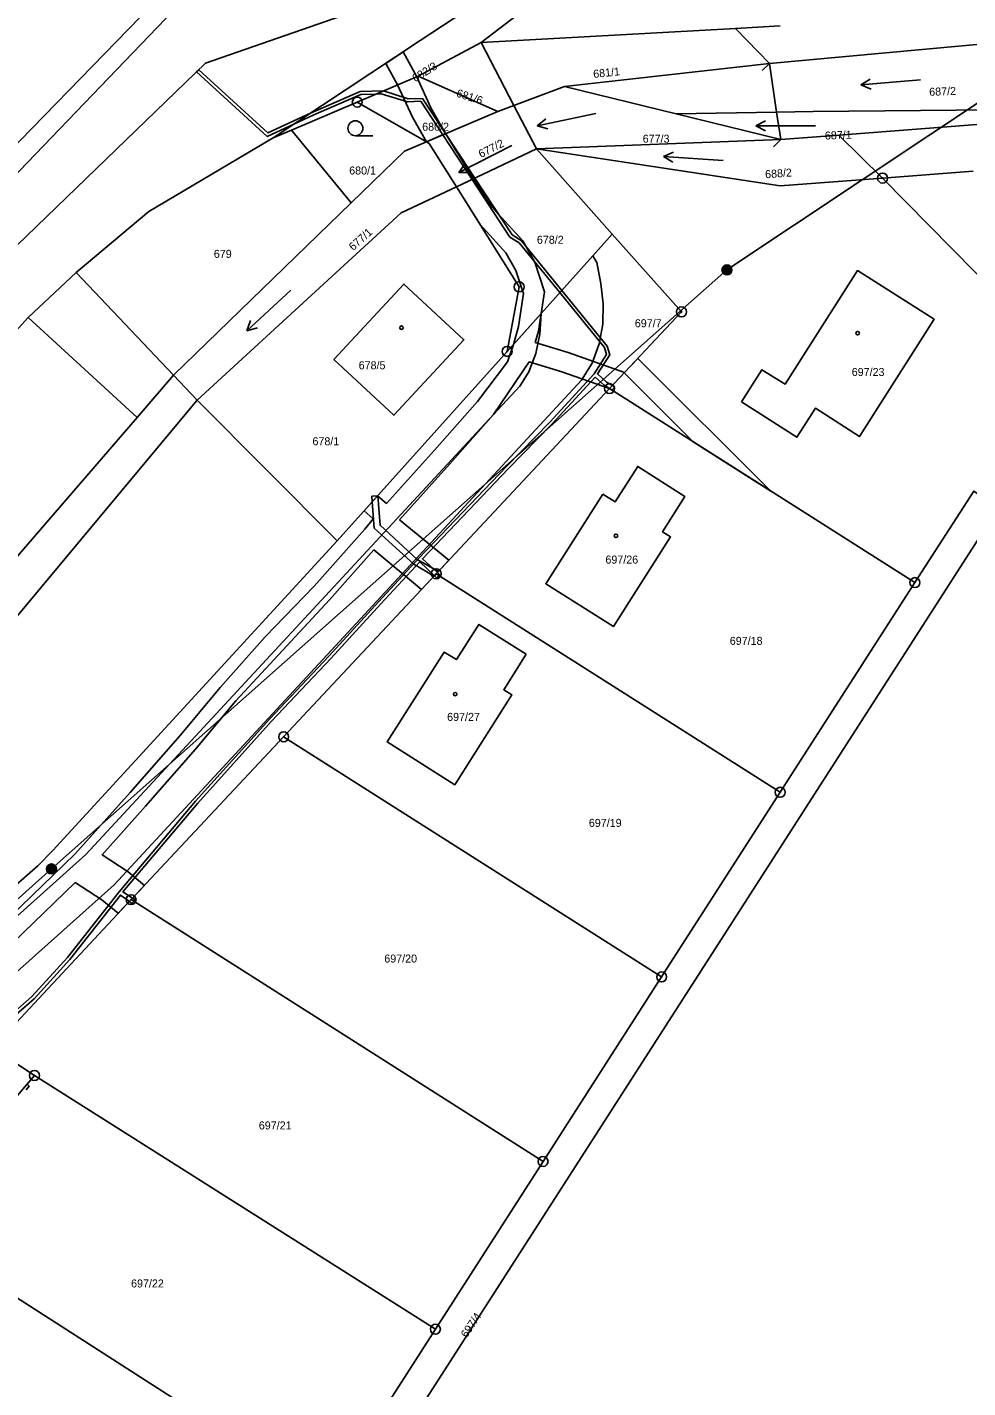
# Model space of a CAD drawing. Extents: x -587171 to -555306, y -1167727 to -1074732.
# Drawn here: x -560808.1 to -560713.8, y -1077994 to -1077857.5 of the extents above; entities that cross this region are included whole.
import ezdxf

# ---------------------------------------------------------------- set-up
doc = ezdxf.new("R2010")
doc.units = 0
for name, color, linetype in [('Hranice parcel', 7, 'Continuous'), ('Parcelní čísla', 7, 'Continuous'), ('Poz předměty', 7, 'Continuous'), ('Vnitřní kresba', 7, 'Continuous'), ('Věcná břemena k části', 7, 'Continuous'), ('Značky bodu BP', 7, 'Continuous'), ('Značky budov', 7, 'Continuous'), ('Značky kultur', 7, 'Continuous')]:
    doc.layers.add(name, color=color, linetype=linetype)

msp = doc.modelspace()

# ---------------------------------------------------------------- linework, layer by layer
at = {"layer": 'Hranice parcel'}
for p, q in [((-560756.08, -1077854.03), (-560762.56, -1077859.03)), ((-560733.66, -1077861.13), (-560679.72, -1077856.25)), ((-560762.56, -1077859.03), (-560737.05, -1077857.63)), ((-560737.05, -1077857.63), (-560732.58, -1077857.38)), ((-560733.66, -1077861.13), (-560737.05, -1077857.63)), ((-560762.56, -1077859.03), (-560768.88, -1077862.42)), ((-560759.28, -1077865.35), (-560762.56, -1077859.03)), ((-560790.19, -1077861.11), (-560821.39, -1077891.23)), ((-560754.21, -1077863.45), (-560733.66, -1077861.13)), ((-560768.88, -1077862.42), (-560774.98, -1077865.02)), ((-560760.9, -1077865.96), (-560768.88, -1077862.42)), ((-560754.21, -1077863.45), (-560759.28, -1077865.35)), ((-560743, -1077866.2), (-560754.21, -1077863.45)), ((-560774.98, -1077865.02), (-560781.58, -1077867.83)), ((-560768.05, -1077869), (-560774.98, -1077865.02)), ((-560726.71, -1077868.33), (-560672, -1077864.07)), ((-560760.9, -1077865.96), (-560768.05, -1077869)), ((-560759.28, -1077865.35), (-560760.9, -1077865.96)), ((-560757.02, -1077869.71), (-560759.28, -1077865.35)), ((-560732.52, -1077868.78), (-560743, -1077866.2)), ((-560781.58, -1077867.83), (-560783.41, -1077868.61)), ((-560775.58, -1077875.11), (-560781.58, -1077867.83)), ((-560757.02, -1077869.71), (-560732.52, -1077868.78)), ((-560732.52, -1077868.78), (-560726.71, -1077868.33)), ((-560726.71, -1077868.33), (-560722.31, -1077872.64)), ((-560765.04, -1077873.51), (-560757.02, -1077869.71)), ((-560749.41, -1077878.26), (-560757.02, -1077869.71)), ((-560713.23, -1077871.95), (-560722.31, -1077872.64)), ((-560722.31, -1077872.64), (-560693.81, -1077901.67)), ((-560793.41, -1077892.41), (-560775.58, -1077875.11)), ((-560749.41, -1077878.26), (-560751.37, -1077880.45)), ((-560756.54, -1077886.22), (-560751.37, -1077880.45)), ((-560793.41, -1077892.41), (-560803.17, -1077882.12)), ((-560759.95, -1077890.02), (-560756.54, -1077886.22)), ((-560776.98, -1077909.03), (-560759.95, -1077890.02)), ((-560791.02, -1077894.93), (-560793.41, -1077892.41)), ((-560767.06, -1077912.33), (-560749.68, -1077893.76)), ((-560749.68, -1077893.76), (-560719.07, -1077913.22)), ((-560791.02, -1077894.93), (-560842.84, -1077957.02)), ((-560776.98, -1077909.03), (-560791.02, -1077894.93)), ((-560768, -1077994.99), (-560710.72, -1077905.75)), ((-560782.36, -1077928.68), (-560767.06, -1077912.33)), ((-560767.06, -1077912.33), (-560732.58, -1077934.25)), ((-560719.07, -1077913.22), (-560732.58, -1077934.25)), ((-560797.66, -1077945.02), (-560782.36, -1077928.68)), ((-560782.36, -1077928.68), (-560744.46, -1077952.77)), ((-560732.58, -1077934.25), (-560744.46, -1077952.77)), ((-560797.66, -1077945.02), (-560756.35, -1077971.28)), ((-560744.46, -1077952.77), (-560756.35, -1077971.28)), ((-560809.85, -1077965.61), (-560807.35, -1077962.66)), ((-560807.35, -1077962.66), (-560767.15, -1077988.11)), ((-560756.35, -1077971.28), (-560767.15, -1077988.11)), ((-560777.96, -1078004.94), (-560820.22, -1077977.81)), ((-560767.15, -1077988.11), (-560777.96, -1078004.94))]:
    msp.add_line(p, q, dxfattribs=at)
for points in [[(-560839.79, -1077904.03), (-560830.06, -1077893.99), (-560794.22, -1077856.67), (-560783.34, -1077845.34)], [(-560831.7, -1077892.42), (-560795.51, -1077855.24), (-560804.32, -1077846.62), (-560836.42, -1077879.93), (-560837.53, -1077878.9), (-560844.57, -1077886.1), (-560839.95, -1077890.45), (-560834.16, -1077895.9), (-560831.33, -1077893.15), (-560831.89, -1077892.61), (-560831.7, -1077892.42)], [(-560759.81, -1077848.36), (-560774.13, -1077855.53), (-560790.19, -1077861.11)], [(-560783.41, -1077868.61), (-560768.67, -1077858.85), (-560757.69, -1077851.58)], [(-560672, -1077864.07), (-560707.75, -1077865.76), (-560729.28, -1077865.96), (-560732.93, -1077866.02), (-560743, -1077866.2)], [(-560783.41, -1077868.61), (-560795.88, -1077876), (-560803.17, -1077882.12)], [(-560768.05, -1077869), (-560770.26, -1077869.94), (-560775.58, -1077875.11)], [(-560765.04, -1077873.51), (-560767.76, -1077869.17), (-560768.05, -1077869)], [(-560722.31, -1077872.64), (-560732.58, -1077873.43), (-560757.02, -1077869.71)], [(-560791.02, -1077894.93), (-560770.59, -1077876.13), (-560765.04, -1077873.51)], [(-560759.95, -1077890.02), (-560758.75, -1077883.55), (-560765.04, -1077873.51)], [(-560749.68, -1077893.76), (-560742.47, -1077886.06), (-560749.41, -1077878.26)], [(-560751.37, -1077880.45), (-560750.95, -1077881.11), (-560750.55, -1077883.22), (-560750.31, -1077885.24), (-560750.36, -1077887.28), (-560750.72, -1077889.27), (-560751.42, -1077891.19), (-560752.5, -1077892.91), (-560799.37, -1077943.53), (-560809.44, -1077952.55), (-560810.66, -1077954.11), (-560811.42, -1077955.96), (-560811.86, -1077957.91), (-560811.93, -1077959.9), (-560811.62, -1077961.87), (-560810.89, -1077963.73), (-560809.85, -1077965.61)], [(-560803.17, -1077882.12), (-560807.98, -1077886.64), (-560824.5, -1077904.81), (-560849.79, -1077930.17)], [(-560736.46, -1077895.08), (-560734.41, -1077891.87), (-560732.08, -1077893.32), (-560724.83, -1077881.92), (-560717.15, -1077886.8), (-560724.62, -1077898.55), (-560729.05, -1077895.73), (-560730.9, -1077898.64), (-560736.46, -1077895.08)], [(-560777.34, -1077890.83), (-560770.3, -1077883.27), (-560764.28, -1077888.86), (-560771.33, -1077896.43), (-560777.34, -1077890.83)], [(-560756.54, -1077886.22), (-560756.66, -1077888.29), (-560757.06, -1077890.24), (-560757.78, -1077892.08), (-560758.67, -1077893.52), (-560761.33, -1077896.34), (-560802.19, -1077940.49), (-560832.27, -1077967.48), (-560829.54, -1077970.6), (-560825.47, -1077966.88), (-560821.58, -1077966.02), (-560819.57, -1077966.1), (-560816.7, -1077966.95), (-560814.91, -1077967.81), (-560813.35, -1077969.09), (-560809.85, -1077965.61)], [(-560836.88, -1077942.81), (-560797.05, -1077896.64), (-560793.41, -1077892.41)], [(-560750.35, -1077904.33), (-560749.12, -1077905.1), (-560746.85, -1077901.56), (-560742.12, -1077904.59), (-560744.37, -1077908.13), (-560743.57, -1077908.64), (-560749.3, -1077917.62), (-560756.08, -1077913.33), (-560750.35, -1077904.33)], [(-560710.72, -1077905.75), (-560713.17, -1077904.03), (-560719.07, -1077913.22)], [(-560834.1, -1077965.37), (-560807, -1077941.64), (-560805.52, -1077940.09), (-560776.98, -1077909.03)], [(-560758.05, -1077920.41), (-560760.3, -1077923.96), (-560759.49, -1077924.47), (-560765.21, -1077933.49), (-560771.97, -1077929.2), (-560766.25, -1077920.18), (-560765.04, -1077920.94), (-560762.78, -1077917.41), (-560758.05, -1077920.41)], [(-560807.35, -1077962.66), (-560811.56, -1077959.88), (-560797.66, -1077945.02)]]:
    msp.add_lwpolyline(points, dxfattribs=at)
at = {"layer": 'Poz předměty'}
for p, q in [((-560737.91, -1077881.85), (-560693.9, -1077852.52)), ((-560805.64, -1077941.94), (-560737.91, -1077881.85)), ((-560872.99, -1078001.92), (-560805.64, -1077941.94))]:
    msp.add_line(p, q, dxfattribs=at)
for centre, radius in [((-560737.91, -1077881.85), 0.5), ((-560737.91, -1077881.85), 0.4), ((-560737.91, -1077881.85), 0.3), ((-560737.91, -1077881.85), 0.2), ((-560737.91, -1077881.85), 0.1), ((-560805.64, -1077941.94), 0.5), ((-560805.64, -1077941.94), 0.4), ((-560805.64, -1077941.94), 0.3), ((-560805.64, -1077941.94), 0.2), ((-560805.64, -1077941.94), 0.1)]:
    msp.add_circle(centre, radius, dxfattribs=at)
at = {"layer": 'Vnitřní kresba'}
for p, q in [((-560734.37, -1077861.84), (-560733.66, -1077861.13)), ((-560733.66, -1077861.13), (-560732.93, -1077866.02)), ((-560732.93, -1077866.02), (-560732.52, -1077868.78)), ((-560733.23, -1077869.49), (-560732.52, -1077868.78)), ((-560797.05, -1077896.64), (-560807.98, -1077886.64))]:
    msp.add_line(p, q, dxfattribs=at)
at = {"layer": 'Věcná břemena k části'}
for points in [[(-560768.05, -1077869), (-560766.13, -1077868.18), (-560767.61, -1077865.59), (-560769, -1077862.47), (-560770.38, -1077859.98), (-560772.11, -1077861.13), (-560770.93, -1077863.29), (-560769.45, -1077866.53)], [(-560781.34, -1077867.24), (-560779.32, -1077866.31), (-560774.62, -1077864.25), (-560773.09, -1077864.21), (-560772.57, -1077864.2), (-560769.93, -1077864.98), (-560768.61, -1077864.94), (-560766.4, -1077868.3), (-560766.12, -1077868.18), (-560768.45, -1077864.64), (-560769.89, -1077864.68), (-560772.34, -1077863.9), (-560774.68, -1077863.95), (-560779.66, -1077866.14), (-560783.95, -1077868.11), (-560790.87, -1077861.77), (-560791.1, -1077861.99), (-560784.01, -1077868.47)], [(-560768.05, -1077869), (-560767.76, -1077869.17), (-560765.04, -1077873.51), (-560763.34, -1077872.7), (-560765.23, -1077869.65), (-560766.13, -1077868.18)], [(-560763.47, -1077872.77), (-560763.2, -1077872.64), (-560766.12, -1077868.18), (-560766.4, -1077868.3)], [(-560759.32, -1077889.32), (-560756.54, -1077886.22), (-560756.22, -1077884.05), (-560757.18, -1077881.06), (-560758.39, -1077878.92), (-560760.88, -1077876.19), (-560761.85, -1077875.03), (-560763.34, -1077872.7), (-560765.04, -1077873.51), (-560762.67, -1077877.29), (-560760.07, -1077880.14), (-560759.08, -1077881.9), (-560758.32, -1077884.23), (-560758.83, -1077887.54)], [(-560758.75, -1077879.12), (-560754.68, -1077884.13), (-560754.47, -1077883.91), (-560758.55, -1077878.9), (-560759.46, -1077878.33), (-560763.2, -1077872.64), (-560763.47, -1077872.77), (-560759.68, -1077878.55)], [(-560746.84, -1077890.73), (-560748.21, -1077892.19), (-560741.3, -1077899.09), (-560733.51, -1077904.04)], [(-560749.14, -1077893.57), (-560749.38, -1077893.44), (-560749.68, -1077893.76), (-560749.45, -1077893.91)], [(-560773.52, -1077904.54), (-560773.48, -1077905.12), (-560772.92, -1077904.5)], [(-560766.85, -1077912.1), (-560768.96, -1077910.9), (-560772.69, -1077907.47), (-560772.92, -1077904.5), (-560773.48, -1077905.12), (-560773.27, -1077907.76), (-560769.32, -1077911.38), (-560767.27, -1077912.56), (-560767.06, -1077912.33)]]:
    msp.add_lwpolyline(points, close=True, dxfattribs=at)
for points in [[(-560809.41, -1077956.73), (-560807.39, -1077954.96), (-560803.81, -1077951.03), (-560798.72, -1077944.56), (-560797.83, -1077945.21), (-560797.57, -1077945.4), (-560797.39, -1077945.19), (-560797.25, -1077945.04), (-560797.52, -1077944.87), (-560798.47, -1077944.25), (-560790.97, -1077935.33), (-560783.57, -1077927.1), (-560777.6, -1077920.79), (-560772.63, -1077915.33), (-560768.72, -1077911.12), (-560767.25, -1077912.54), (-560767.01, -1077912.77), (-560766.77, -1077912.52), (-560766.69, -1077912.44), (-560766.95, -1077912.21), (-560768.44, -1077910.83), (-560759.8, -1077901.78), (-560755.46, -1077897.32), (-560751.14, -1077892.61), (-560750.23, -1077893.42), (-560749.68, -1077893.76), (-560749.38, -1077893.44), (-560749.99, -1077893.1), (-560750.9, -1077892.29), (-560749.66, -1077890.36), (-560749.94, -1077889.49), (-560754.47, -1077883.91), (-560754.68, -1077884.13), (-560750.2, -1077889.63), (-560749.98, -1077890.32), (-560751.24, -1077892.27), (-560755.68, -1077897.12), (-560760.02, -1077901.58), (-560768.8, -1077910.77), (-560772.85, -1077915.13), (-560777.82, -1077920.59), (-560783.79, -1077926.9), (-560791.19, -1077935.13), (-560798.84, -1077944.22), (-560804.03, -1077950.83), (-560807.6, -1077954.74), (-560809.61, -1077956.51)], [(-560810.56, -1077950.36), (-560803.27, -1077943.3), (-560800.59, -1077945.05), (-560798.94, -1077946.39), (-560797.66, -1077945.02), (-560796.32, -1077943.59), (-560797.94, -1077942.24), (-560800.57, -1077940.52), (-560796.21, -1077935.64), (-560791.19, -1077929.91), (-560787.15, -1077925.07), (-560777.77, -1077914.96), (-560773.31, -1077909.94), (-560768.55, -1077913.92), (-560767.06, -1077912.33), (-560765.79, -1077910.97), (-560770.73, -1077906.91), (-560765.69, -1077901.29), (-560761.33, -1077896.34), (-560757.75, -1077891.08), (-560754.47, -1077892.07), (-560749.68, -1077893.76), (-560748.17, -1077892.14), (-560753.83, -1077890.13), (-560757.13, -1077889.14), (-560756.81, -1077887.98), (-560756.54, -1077886.22), (-560759.32, -1077889.32), (-560759.93, -1077891.06), (-560762.93, -1077895.04), (-560767.23, -1077899.93), (-560772.04, -1077905.28), (-560772.94, -1077904.52), (-560774.29, -1077906.03), (-560773.37, -1077906.81), (-560774.22, -1077907.85), (-560779.29, -1077913.56), (-560784.2, -1077918.66), (-560788.71, -1077923.73), (-560792.75, -1077928.57), (-560797.75, -1077934.28), (-560803.29, -1077940.46), (-560811.98, -1077948.86)], [(-560808.19, -1077964.1), (-560807.88, -1077963.74), (-560808.08, -1077963.52)]]:
    msp.add_lwpolyline(points, dxfattribs=at)
at = {"layer": 'Značky bodu BP'}
for centre, radius in [((-560774.98, -1077865.02), 0.5), ((-560774.98, -1077865.02), 0.0303), ((-560722.31, -1077872.64), 0.5), ((-560722.31, -1077872.64), 0.0303), ((-560758.75, -1077883.55), 0.5), ((-560758.75, -1077883.55), 0.0303), ((-560742.47, -1077886.06), 0.5), ((-560742.47, -1077886.06), 0.0303), ((-560759.95, -1077890.02), 0.5), ((-560759.95, -1077890.02), 0.0303), ((-560749.68, -1077893.76), 0.5), ((-560749.68, -1077893.76), 0.0303), ((-560767.06, -1077912.33), 0.5), ((-560767.06, -1077912.33), 0.0303), ((-560719.07, -1077913.22), 0.5), ((-560719.07, -1077913.22), 0.0303), ((-560782.36, -1077928.68), 0.5), ((-560782.36, -1077928.68), 0.0303), ((-560732.58, -1077934.25), 0.5), ((-560732.58, -1077934.25), 0.0303), ((-560797.66, -1077945.02), 0.5), ((-560797.66, -1077945.02), 0.0303), ((-560744.46, -1077952.77), 0.5), ((-560744.46, -1077952.77), 0.0303), ((-560807.35, -1077962.66), 0.5), ((-560807.35, -1077962.66), 0.0303), ((-560756.35, -1077971.28), 0.5), ((-560756.35, -1077971.28), 0.0303), ((-560767.15, -1077988.11), 0.5), ((-560767.15, -1077988.11), 0.0303)]:
    msp.add_circle(centre, radius, dxfattribs=at)
at = {"layer": 'Značky budov'}
for centre in [(-560770.55, -1077887.65), (-560724.81, -1077888.2), (-560749.04, -1077908.53), (-560765.16, -1077924.4)]:
    msp.add_circle(centre, 0.175, dxfattribs=at)
at = {"layer": 'Značky kultur'}
for p, q in [((-560724.49, -1077863.29), (-560723.56, -1077862.71)), ((-560718.51, -1077862.77), (-560724.49, -1077863.29)), ((-560724.49, -1077863.29), (-560723.47, -1077863.71)), ((-560751.06, -1077866.15), (-560756.93, -1077867.4)), ((-560756.93, -1077867.4), (-560756.08, -1077866.71)), ((-560756.93, -1077867.4), (-560755.87, -1077867.69)), ((-560735.02, -1077867.39), (-560734.04, -1077866.89)), ((-560729.02, -1077867.39), (-560735.02, -1077867.39)), ((-560735.02, -1077867.39), (-560734.04, -1077867.89)), ((-560775.17, -1077868.39), (-560773.42, -1077868.39)), ((-560759.47, -1077869.36), (-560764.81, -1077872.08)), ((-560744.29, -1077870.47), (-560743.28, -1077870.04)), ((-560738.3, -1077870.89), (-560744.29, -1077870.47)), ((-560744.29, -1077870.47), (-560743.35, -1077871.04)), ((-560764.81, -1077872.08), (-560764.17, -1077871.19)), ((-560764.81, -1077872.08), (-560763.71, -1077872.08)), ((-560781.65, -1077883.88), (-560786.04, -1077887.97)), ((-560786.04, -1077887.97), (-560785.67, -1077886.94)), ((-560786.04, -1077887.97), (-560784.99, -1077887.67))]:
    msp.add_line(p, q, dxfattribs=at)
msp.add_circle((-560775.17, -1077867.64), 0.75, dxfattribs=at)

# ---------------------------------------------------------------- texts
at = {"layer": 'Parcelní čísla'}
for s, rotation, p in [('682/3', 32, (-560769.16, -1077863.05)), ('681/1', 6, (-560751.28, -1077862.6)), ('681/6', 342, (-560765.11, -1077864.45)), ('687/2', 2, (-560717.62, -1077864.39)), ('687/1', 2, (-560728.08, -1077868.78)), ('677/2', 27, (-560762.57, -1077870.64)), ('688/2', 4, (-560734.06, -1077872.66)), ('677/1', 42, (-560775.39, -1077879.97)), ('697/4', 56, (-560764, -1077989.03))]:
    msp.add_text(s, height=0.803, rotation=rotation, dxfattribs=at).set_placement(p)
for s, p in [('680/2', (-560768.47, -1077867.89)), ('677/3', (-560746.36, -1077869.09)), ('680/1', (-560775.79, -1077872.28)), ('678/2', (-560756.97, -1077879.23)), ('679', (-560789.36, -1077880.64)), ('697/7', (-560747.15, -1077887.6)), ('678/5', (-560774.84, -1077891.82)), ('697/23', (-560725.4, -1077892.49)), ('678/1', (-560779.47, -1077899.44)), ('697/26', (-560750.1, -1077911.31)), ('697/18', (-560737.63, -1077919.46)), ('697/27', (-560765.97, -1077927.09)), ('697/19', (-560751.76, -1077937.72)), ('697/20', (-560772.27, -1077951.33)), ('697/21', (-560784.85, -1077968.07)), ('697/22', (-560797.66, -1077983.92))]:
    msp.add_text(s, height=0.803, dxfattribs=at).set_placement(p)

doc.saveas('drawing.dxf')
